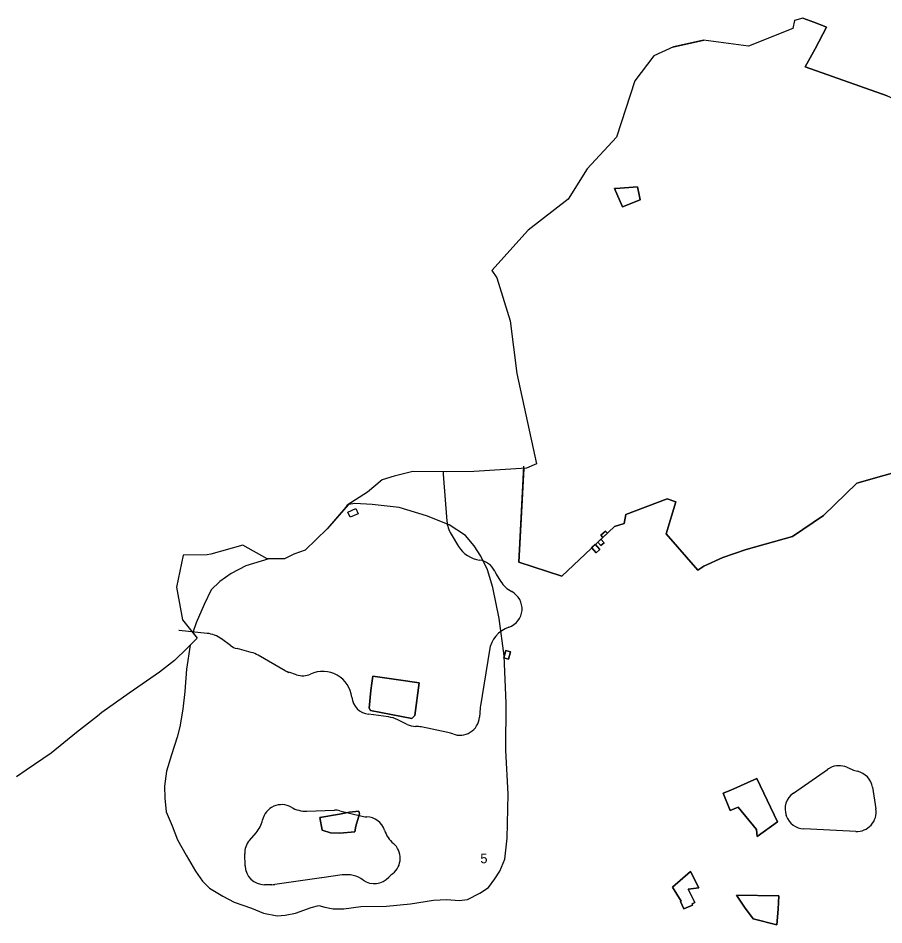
# Model space of a CAD drawing. Extents: x -445049 to -436194, y -1142460 to -1129816.
# Drawn here: x -443912 to -443023, y -1132330 to -1131398 of the extents above; entities that cross this region are included whole.
import ezdxf

# ---------------------------------------------------------------- set-up
doc = ezdxf.new("R2010")
doc.units = 0
for name, color, linetype in [('Vrstva 23', 7, 'Continuous'), ('Vrstva 51', 7, 'Continuous'), ('Vrstva 7', 7, 'Continuous'), ('Vrstva 8', 7, 'Continuous'), ('Vrstva 9', 7, 'Continuous')]:
    doc.layers.add(name, color=color, linetype=linetype)

msp = doc.modelspace()

# ---------------------------------------------------------------- linework, layer by layer
at = {"layer": 'Vrstva 23'}
for p, q in [((-443475.15, -1131866.8), (-443471.51, -1131914.89)), ((-443467.2, -1131928.26), (-443459.47, -1131940.92)), ((-443420.75, -1131969.45), (-443416.3, -1131976.64)), ((-443717.67, -1132030.24), (-443746.42, -1132027.28)), ((-443693.62, -1132042.73), (-443703.08, -1132035.84)), ((-443672.36, -1132049.78), (-443686.98, -1132045.89)), ((-443427.86, -1132047.57), (-443437.12, -1132104.61)), ((-443637.39, -1132068.59), (-443665.19, -1132052.72)), ((-443625.82, -1132072.79), (-443633.65, -1132070.24)), ((-443437.42, -1132107.15), (-443438.12, -1132116.33)), ((-443531.32, -1132116.07), (-443551.89, -1132113.37)), ((-443512.32, -1132123.69), (-443521.9, -1132118.94)), ((-443470.35, -1132131.96), (-443497.76, -1132126.37)), ((-443115.67, -1132194.27), (-443080.76, -1132169.96)), ((-443078.4, -1132168.54), (-443077.85, -1132168.26)), ((-443060.79, -1132167.75), (-443055.44, -1132170.08)), ((-443034.44, -1132188.31), (-443030.95, -1132210.57)), ((-443615.16, -1132212.82), (-443586.81, -1132211.84)), ((-443581.29, -1132212.42), (-443560.02, -1132217.71)), ((-443122.96, -1132217.73), (-443123.1, -1132217.33)), ((-443674.24, -1132242.99), (-443667.43, -1132235.14)), ((-443084.92, -1132232.05), (-443105.07, -1132231.06)), ((-443051.67, -1132233.64), (-443084.89, -1132232.05)), ((-443678.74, -1132268.92), (-443679.12, -1132256.7)), ((-443600.21, -1132281.21), (-443648.27, -1132288.12)), ((-443578.93, -1132278.3), (-443600.01, -1132281.18)), ((-443651.15, -1132288.32), (-443658.79, -1132288.31))]:
    msp.add_line(p, q, dxfattribs=at)
for centre, radius, start, end in [((-443445.23, -1131864.54), 30, 179.2383, 184.32397), ((-443441.59, -1131912.63), 30, 184.32397, 211.39988), ((-443433.87, -1131925.29), 30, 211.39988, 262.34732), ((-443440.53, -1131974.85), 20, 25.04438, 82.34732), ((-443395.23, -1131953.68), 30, 205.04438, 211.71501), ((-443390.78, -1131960.87), 30, 211.71501, 241.97229), ((-443414.28, -1132005.01), 20, 288.69459, 61.97229), ((-443749.5, -1132057.12), 30, 84.11683, 84.49329), ((-443720.75, -1132060.09), 30, 53.93356, 84.11683), ((-443398.25, -1132052.37), 30, 108.69459, 170.78246), ((-443681.85, -1132026.56), 20, 233.93356, 255.12335), ((-443680.06, -1132078.77), 30, 60.27268, 75.12335), ((-443627.47, -1132051.22), 20, 240.27268, 252.00897), ((-443598.96, -1132099.29), 30, 6.59723, 114.43788), ((-443619.64, -1132053.76), 20, 252.00897, 294.43788), ((-443549.29, -1132093.54), 20, 186.59723, 262.51376), ((-443407.51, -1132109.42), 30, 170.78246, 175.65272), ((-443535.23, -1132145.82), 30, 63.62647, 82.51376), ((-443458.06, -1132114.82), 20, 248.55867, 355.65272), ((-443503.44, -1132105.77), 20, 243.62647, 269.6398), ((-443503.75, -1132155.77), 30, 78.47906, 89.6398), ((-443476.34, -1132161.36), 30, 68.55867, 78.47906), ((-443069.33, -1132186.37), 20, 116.98135, 124.856), ((-443068.78, -1132186.09), 20, 66.47035, 116.98135), ((-443043.46, -1132142.57), 30, 246.47035, 257.5946), ((-443054.2, -1132191.41), 20, 8.919, 77.5946), ((-443104.24, -1132210.68), 20, 124.856, 199.4132), ((-443641.24, -1132226.11), 20, 59.94181, 167.73285), ((-443616.2, -1132182.83), 30, 239.94181, 271.9806), ((-443586.12, -1132231.82), 20, 76.02756, 91.9806), ((-443552.77, -1132188.6), 30, 256.02756, 267.99116), ((-443554.53, -1132238.56), 20, 18.04103, 87.99116), ((-443104.09, -1132211.09), 20, 199.4132, 267.18654), ((-443050.71, -1132213.67), 20, 267.25919, 8.919), ((-443690.1, -1132215.49), 30, 319.07827, 347.73285), ((-443506.98, -1132223.08), 30, 198.04103, 229.61742), ((-443083.94, -1132212.08), 20, 267.18654, 267.25919), ((-443659.13, -1132256.09), 20, 139.07827, 181.75911), ((-443539.38, -1132261.17), 20, 307.92905, 49.61742), ((-443658.75, -1132268.31), 20, 181.75911, 269.90427), ((-443595.95, -1132310.91), 30, 97.78127, 98.17651), ((-443574.86, -1132308.03), 30, 54.61036, 97.78127), ((-443545.91, -1132267.27), 20, 234.61036, 318.17982), ((-443508.64, -1132300.61), 30, 127.92905, 138.17982), ((-443651.12, -1132268.32), 20, 269.90427, 278.17651)]:
    msp.add_arc(centre, radius, start, end, dxfattribs=at)
at = {"layer": 'Vrstva 51'}
msp.add_lwpolyline([(-443572.42, -1131897.76), (-443594.49, -1131922.99), (-443616.95, -1131944.89), (-443628.48, -1131948.87), (-443638.18, -1131953.77), (-443654.2, -1131953.68), (-443677.95, -1131960.91), (-443692.88, -1131968.79), (-443704.54, -1131976.92), (-443713.38, -1131985.67), (-443720.65, -1132000.68), (-443729.01, -1132019.29), (-443732.41, -1132029.28), (-443727.75, -1132035.14), (-443735.16, -1132042.47), (-443738.73, -1132066.87), (-443740.48, -1132090.07), (-443742.64, -1132107.92), (-443745.64, -1132126.12), (-443748.5, -1132136.96), (-443754.36, -1132154.94), (-443759.31, -1132171.76), (-443761.29, -1132187.17), (-443760.98, -1132199.47), (-443759.58, -1132213.5), (-443753.7, -1132227.86), (-443748.23, -1132242.19), (-443739.18, -1132258.01), (-443729.76, -1132274.28), (-443722.36, -1132284.66), (-443715.11, -1132291.76), (-443701.42, -1132300.15), (-443690.01, -1132306.33), (-443672.06, -1132312.6), (-443659.74, -1132317.62), (-443645.62, -1132320.32), (-443637.39, -1132319.71), (-443626.99, -1132317.62), (-443611.01, -1132311.87), (-443603.06, -1132309.6), (-443596.64, -1132311.31), (-443588.18, -1132313.17), (-443577.13, -1132313.19), (-443559.75, -1132310.81), (-443533.52, -1132310.32), (-443508.79, -1132308.09), (-443485.15, -1132304.14), (-443471.6, -1132303.52), (-443458.98, -1132304.46), (-443450.31, -1132303.48), (-443437.55, -1132297.07), (-443428.91, -1132291.17), (-443422.1, -1132282.27), (-443417.01, -1132274.46), (-443411.99, -1132262.15), (-443409.56, -1132240.63), (-443408.6, -1132195.27), (-443410.94, -1132150.06), (-443410.58, -1132101.78), (-443412.67, -1132053.32), (-443417.96, -1132014.85), (-443424.18, -1131983.27), (-443429.76, -1131964.83), (-443436.48, -1131950.82), (-443443.48, -1131940.47), (-443452.49, -1131929.56), (-443469.29, -1131918.88), (-443492.32, -1131909.37), (-443520.35, -1131901.12), (-443548.35, -1131897.79), (-443565.88, -1131896.88)], close=True, dxfattribs=at)
at = {"layer": 'Vrstva 7'}
for points in [[(-443106.12, -1131398.41), (-443114.71, -1131400.93), (-443116.42, -1131408.94), (-443161.64, -1131427.27), (-443207.88, -1131421.18), (-443238.79, -1131427.9), (-443259.15, -1131437.15), (-443278.58, -1131462.76), (-443297.46, -1131520.49), (-443327.59, -1131553.33), (-443347.05, -1131584.42), (-443388.09, -1131616.17), (-443425.49, -1131657.44), (-443420.03, -1131665.04), (-443406.44, -1131709.38), (-443399.66, -1131763.33), (-443379.47, -1131856.15), (-443389.59, -1131860.69), (-443443.78, -1131863.94), (-443472.08, -1131864.36), (-443506.55, -1131863.91), (-443525.54, -1131868.7), (-443537.86, -1131872.43), (-443552.93, -1131885.12), (-443573.87, -1131898.7), (-443575.38, -1131900.47), (-443594.49, -1131922.99), (-443616.95, -1131944.89), (-443628.48, -1131948.87), (-443638.18, -1131953.77), (-443655.99, -1131953.67), (-443680.94, -1131939.56), (-443713.85, -1131949.02), (-443717.48, -1131949.61), (-443742.21, -1131949.8), (-443749.19, -1131982.83), (-443748.48, -1131986.52), (-443742.79, -1132016.22), (-443727.75, -1132035.14), (-443740.49, -1132047.74), (-443748.61, -1132055.57), (-443751.12, -1132058), (-443766.44, -1132070.14), (-443797.62, -1132091.8), (-443825.8, -1132111.44), (-443830.09, -1132115.31), (-443851.84, -1132132), (-443877.88, -1132153.33), (-443903.47, -1132170.82), (-443913.53, -1132177.67)], [(-443019.31, -1131478.11), (-443103.67, -1131448.32), (-443093.18, -1131429.88), (-443081.74, -1131407.73), (-443084.15, -1131406.8), (-443094.83, -1131402.72), (-443106.12, -1131398.41), (-443114.71, -1131400.93), (-443114.71, -1131400.93), (-443116.42, -1131408.94), (-443161.64, -1131427.27), (-443207.88, -1131421.18), (-443238.79, -1131427.9)], [(-443019.31, -1131478.11), (-443103.67, -1131448.32), (-443093.18, -1131429.88), (-443081.74, -1131407.73), (-443084.15, -1131406.8), (-443094.83, -1131402.72), (-443106.12, -1131398.41), (-443114.71, -1131400.93), (-443114.71, -1131400.93)], [(-443106.12, -1131398.41), (-443094.83, -1131402.72), (-443084.15, -1131406.8), (-443081.74, -1131407.73), (-443093.18, -1131429.88), (-443103.67, -1131448.32), (-443019.31, -1131478.11), (-442974.53, -1131497.84), (-442902.15, -1131529.1), (-442888.68, -1131535.01), (-442886.09, -1131536.13), (-442927.75, -1131581.75), (-442952.33, -1131605.18), (-442926.2, -1131613.08), (-442916.62, -1131615.98), (-442893.46, -1131628.44), (-442888.22, -1131631.26), (-442860.09, -1131646.4), (-442799.95, -1131665.86), (-442788.53, -1131669.56), (-442758.56, -1131679.26), (-442813.44, -1131728.66), (-442858.75, -1131769.44)], [(-443114.71, -1131400.93), (-443116.42, -1131408.94), (-443161.64, -1131427.27), (-443207.88, -1131421.18), (-443238.79, -1131427.9), (-443259.15, -1131437.15), (-443278.58, -1131462.76), (-443297.46, -1131520.49), (-443327.59, -1131553.33), (-443347.05, -1131584.42), (-443388.09, -1131616.17), (-443425.49, -1131657.44), (-443420.03, -1131665.04), (-443406.44, -1131709.38), (-443399.66, -1131763.33), (-443379.47, -1131856.15), (-443389.59, -1131860.69), (-443443.78, -1131863.94), (-443472.08, -1131864.36), (-443506.55, -1131863.91), (-443525.54, -1131868.7), (-443537.86, -1131872.43), (-443552.93, -1131885.12), (-443573.87, -1131898.7), (-443575.38, -1131900.47), (-443594.49, -1131922.99), (-443616.95, -1131944.89), (-443628.48, -1131948.87), (-443638.18, -1131953.77), (-443655.99, -1131953.67), (-443680.94, -1131939.56), (-443713.85, -1131949.02), (-443717.48, -1131949.61), (-443742.21, -1131949.8), (-443749.19, -1131982.83), (-443748.48, -1131986.52), (-443742.79, -1132016.22), (-443727.75, -1132035.14), (-443740.49, -1132047.74), (-443748.61, -1132055.57), (-443751.12, -1132058), (-443766.44, -1132070.14), (-443797.62, -1132091.8), (-443825.8, -1132111.44), (-443830.09, -1132115.31), (-443851.84, -1132132), (-443877.88, -1132153.33), (-443903.47, -1132170.82), (-443913.53, -1132177.67)], [(-443114.76, -1131400.94), (-443114.71, -1131400.93)], [(-443239.89, -1131428.14), (-443207.7, -1131421.15)], [(-443238.79, -1131427.9), (-443259.15, -1131437.15), (-443278.58, -1131462.76), (-443297.46, -1131520.49), (-443327.59, -1131553.33), (-443347.05, -1131584.42), (-443388.09, -1131616.17), (-443425.49, -1131657.44), (-443420.03, -1131665.04), (-443406.44, -1131709.38), (-443399.66, -1131763.33), (-443379.47, -1131856.15), (-443389.59, -1131860.69), (-443443.78, -1131863.94), (-443472.08, -1131864.36), (-443506.55, -1131863.91), (-443525.54, -1131868.7), (-443537.86, -1131872.43), (-443552.93, -1131885.12), (-443573.87, -1131898.7), (-443575.38, -1131900.47), (-443594.49, -1131922.99), (-443616.95, -1131944.89), (-443628.48, -1131948.87), (-443638.18, -1131953.77), (-443655.99, -1131953.67), (-443680.94, -1131939.56), (-443713.85, -1131949.02), (-443717.48, -1131949.61), (-443742.21, -1131949.8), (-443749.19, -1131982.83), (-443748.48, -1131986.52), (-443742.79, -1132016.22), (-443727.75, -1132035.14), (-443740.49, -1132047.74), (-443748.61, -1132055.57), (-443751.12, -1132058), (-443766.44, -1132070.14), (-443797.62, -1132091.8), (-443825.8, -1132111.44), (-443830.09, -1132115.31), (-443851.84, -1132132), (-443877.88, -1132153.33), (-443903.47, -1132170.82), (-443913.53, -1132177.67)], [(-443275.68, -1131571.49), (-443273.93, -1131579.97), (-443272.88, -1131585.04), (-443291.32, -1131592.19), (-443299.38, -1131573.45), (-443297.91, -1131573.32), (-443275.68, -1131571.49)], [(-443291.32, -1131592.19), (-443299.38, -1131573.45), (-443297.91, -1131573.32), (-443275.68, -1131571.49), (-443273.93, -1131579.97), (-443272.88, -1131585.04), (-443291.32, -1131592.19)], [(-443273.93, -1131579.97), (-443272.88, -1131585.04), (-443291.32, -1131592.19), (-443299.38, -1131573.45), (-443297.91, -1131573.32), (-443275.68, -1131571.49), (-443273.93, -1131579.97)], [(-443275.68, -1131571.49), (-443273.93, -1131579.97), (-443272.88, -1131585.04), (-443291.32, -1131592.19), (-443299.38, -1131573.45), (-443297.91, -1131573.32), (-443275.68, -1131571.49)], [(-443570.89, -1131910.87), (-443573.15, -1131905.64), (-443564.98, -1131902.12), (-443562.72, -1131907.35), (-443570.89, -1131910.87)], [(-443308.59, -1131925.1), (-443306.55, -1131927.36), (-443311.4, -1131931.75), (-443313.45, -1131929.49), (-443308.59, -1131925.1)], [(-443319.06, -1131938.68), (-443314.27, -1131943.98), (-443318.05, -1131947.4), (-443322.85, -1131942.1), (-443319.06, -1131938.68)], [(-443313.28, -1131933.45), (-443309.96, -1131937.12), (-443313.3, -1131940.14), (-443316.62, -1131936.47), (-443313.28, -1131933.45)], [(-443406.13, -1132049.27), (-443408.23, -1132056.78), (-443412.98, -1132055.45), (-443410.88, -1132047.95), (-443406.13, -1132049.27)], [(-443499.8, -1132080.89), (-443504.4, -1132114.58), (-443507.45, -1132117.77), (-443549.76, -1132109.44), (-443551.21, -1132106.87), (-443549.45, -1132088.95), (-443548.71, -1132081.39), (-443547.68, -1132074.2), (-443521.17, -1132078), (-443499.8, -1132080.89)], [(-443521.17, -1132078), (-443499.8, -1132080.89), (-443504.4, -1132114.58), (-443507.45, -1132117.77), (-443549.76, -1132109.44), (-443551.21, -1132106.87), (-443549.45, -1132088.95), (-443548.71, -1132081.39), (-443547.68, -1132074.2), (-443521.17, -1132078)], [(-443499.8, -1132080.89), (-443504.4, -1132114.58), (-443507.45, -1132117.77), (-443549.76, -1132109.44), (-443551.21, -1132106.87), (-443549.45, -1132088.95), (-443548.71, -1132081.39), (-443547.68, -1132074.2), (-443521.17, -1132078), (-443499.8, -1132080.89)], [(-443548.71, -1132081.39), (-443547.68, -1132074.2), (-443521.17, -1132078), (-443499.8, -1132080.89), (-443504.4, -1132114.58), (-443507.45, -1132117.77), (-443549.76, -1132109.44), (-443551.21, -1132106.87), (-443549.45, -1132088.95), (-443548.71, -1132081.39)], [(-443153.2, -1132179.22), (-443131.83, -1132223.89), (-443153.02, -1132238.75), (-443153.54, -1132231.61), (-443172.52, -1132208.83), (-443180.71, -1132212.05), (-443187.66, -1132194.36), (-443179.84, -1132191.22), (-443153.2, -1132179.22)], [(-443172.52, -1132208.83), (-443180.71, -1132212.05), (-443187.66, -1132194.36), (-443179.84, -1132191.22), (-443153.2, -1132179.22), (-443131.83, -1132223.89), (-443153.02, -1132238.75), (-443153.54, -1132231.61), (-443172.52, -1132208.83)], [(-443153.54, -1132231.61), (-443172.52, -1132208.83), (-443180.71, -1132212.05), (-443187.66, -1132194.36), (-443179.84, -1132191.22), (-443153.2, -1132179.22), (-443131.83, -1132223.89), (-443153.02, -1132238.75), (-443153.54, -1132231.61)], [(-443131.83, -1132223.89), (-443153.02, -1132238.75), (-443153.54, -1132231.61), (-443172.52, -1132208.83), (-443180.71, -1132212.05), (-443187.66, -1132194.36), (-443179.84, -1132191.22), (-443153.2, -1132179.22), (-443131.83, -1132223.89)], [(-443562.02, -1132212.92), (-443561.38, -1132215.63), (-443564.99, -1132228.34), (-443566.01, -1132233.97), (-443581.52, -1132235.27), (-443591.13, -1132235.01), (-443599.54, -1132232.26), (-443601.92, -1132219.46), (-443581.84, -1132215.84), (-443571.49, -1132213.97), (-443562.02, -1132212.92)], [(-443581.84, -1132215.84), (-443571.49, -1132213.97), (-443562.02, -1132212.92), (-443561.38, -1132215.63), (-443564.99, -1132228.34), (-443566.01, -1132233.97), (-443581.52, -1132235.27), (-443591.13, -1132235.01), (-443599.54, -1132232.26), (-443601.92, -1132219.46), (-443581.84, -1132215.84)], [(-443601.92, -1132219.46), (-443581.84, -1132215.84), (-443571.49, -1132213.97), (-443562.02, -1132212.92), (-443561.38, -1132215.63), (-443564.99, -1132228.34), (-443566.01, -1132233.97), (-443581.52, -1132235.27), (-443591.13, -1132235.01), (-443599.54, -1132232.26), (-443601.92, -1132219.46)], [(-443599.54, -1132232.26), (-443601.92, -1132219.46), (-443581.84, -1132215.84), (-443571.49, -1132213.97), (-443562.02, -1132212.92), (-443561.38, -1132215.63), (-443564.99, -1132228.34), (-443566.01, -1132233.97), (-443581.52, -1132235.27), (-443591.13, -1132235.01), (-443599.54, -1132232.26)], [(-443221.28, -1132274.81), (-443212.79, -1132291.62), (-443223.56, -1132293.08), (-443216.83, -1132306.64), (-443219.67, -1132308.05), (-443219.17, -1132309.21), (-443228.34, -1132313.19), (-443231.7, -1132305.54), (-443231.03, -1132305.26), (-443239.73, -1132290.98), (-443221.28, -1132274.81)], [(-443239.73, -1132290.98), (-443221.28, -1132274.81), (-443212.79, -1132291.62), (-443223.56, -1132293.08), (-443216.83, -1132306.64), (-443219.67, -1132308.05), (-443219.17, -1132309.21), (-443228.34, -1132313.19), (-443231.7, -1132305.54), (-443231.03, -1132305.26), (-443239.73, -1132290.98)], [(-443219.17, -1132309.21), (-443228.34, -1132313.19), (-443231.7, -1132305.54), (-443231.03, -1132305.26), (-443239.73, -1132290.98), (-443221.28, -1132274.81), (-443212.79, -1132291.62), (-443223.56, -1132293.08), (-443216.83, -1132306.64), (-443219.67, -1132308.05), (-443219.17, -1132309.21)], [(-443219.67, -1132308.05), (-443219.17, -1132309.21), (-443228.34, -1132313.19), (-443231.7, -1132305.54), (-443231.03, -1132305.26), (-443239.73, -1132290.98), (-443221.28, -1132274.81), (-443212.79, -1132291.62), (-443223.56, -1132293.08), (-443216.83, -1132306.64), (-443219.67, -1132308.05)], [(-443130.57, -1132299.65), (-443131.31, -1132313.51), (-443132.73, -1132329.58), (-443157.13, -1132323.38), (-443165.76, -1132311.33), (-443174.05, -1132299.19), (-443130.57, -1132299.65)], [(-443174.05, -1132299.19), (-443130.57, -1132299.65), (-443131.31, -1132313.51), (-443132.73, -1132329.58), (-443157.13, -1132323.38), (-443165.76, -1132311.33), (-443174.05, -1132299.19)], [(-443165.76, -1132311.33), (-443174.05, -1132299.19), (-443130.57, -1132299.65), (-443131.31, -1132313.51), (-443132.73, -1132329.58), (-443157.13, -1132323.38), (-443165.76, -1132311.33)], [(-443174.05, -1132299.19), (-443130.57, -1132299.65), (-443131.31, -1132313.51), (-443132.73, -1132329.58), (-443157.13, -1132323.38), (-443165.76, -1132311.33), (-443174.05, -1132299.19)]]:
    msp.add_lwpolyline(points, dxfattribs=at)
for points in [[(-443275.68, -1131571.49), (-443297.91, -1131573.32), (-443299.38, -1131573.45), (-443291.32, -1131592.19), (-443272.88, -1131585.04), (-443273.93, -1131579.97)], [(-443573.15, -1131905.64), (-443564.98, -1131902.12), (-443562.72, -1131907.35), (-443570.89, -1131910.87)], [(-443308.59, -1131925.1), (-443313.45, -1131929.49), (-443311.4, -1131931.75), (-443306.55, -1131927.36)], [(-443319.06, -1131938.68), (-443322.85, -1131942.1), (-443318.05, -1131947.4), (-443314.27, -1131943.98)], [(-443313.28, -1131933.45), (-443316.62, -1131936.47), (-443313.3, -1131940.14), (-443309.96, -1131937.12)], [(-443406.13, -1132049.27), (-443410.88, -1132047.95), (-443412.98, -1132055.45), (-443408.23, -1132056.78)], [(-443499.8, -1132080.89), (-443521.17, -1132078), (-443547.68, -1132074.2), (-443548.71, -1132081.39), (-443549.45, -1132088.95), (-443551.21, -1132106.87), (-443549.76, -1132109.44), (-443507.45, -1132117.77), (-443504.4, -1132114.58)], [(-443153.2, -1132179.22), (-443179.84, -1132191.22), (-443187.66, -1132194.36), (-443180.71, -1132212.05), (-443172.52, -1132208.83), (-443153.54, -1132231.61), (-443153.02, -1132238.75), (-443131.83, -1132223.89)], [(-443562.02, -1132212.92), (-443571.49, -1132213.97), (-443581.84, -1132215.84), (-443601.92, -1132219.46), (-443599.54, -1132232.26), (-443591.13, -1132235.01), (-443581.52, -1132235.27), (-443566.01, -1132233.97), (-443564.99, -1132228.34), (-443561.38, -1132215.63)], [(-443221.28, -1132274.81), (-443239.73, -1132290.98), (-443231.03, -1132305.26), (-443231.7, -1132305.54), (-443228.34, -1132313.19), (-443219.17, -1132309.21), (-443219.67, -1132308.05), (-443216.83, -1132306.64), (-443223.56, -1132293.08), (-443212.79, -1132291.62)], [(-443130.57, -1132299.65), (-443174.05, -1132299.19), (-443165.76, -1132311.33), (-443157.13, -1132323.38), (-443132.73, -1132329.58), (-443131.31, -1132313.51)]]:
    msp.add_lwpolyline(points, close=True, dxfattribs=at)
at = {"layer": 'Vrstva 8'}
msp.add_lwpolyline([(-443392.54, -1131860.87), (-443397.48, -1131957.17), (-443353.42, -1131971.39), (-443299.24, -1131920.46), (-443289.59, -1131917.32), (-443287.89, -1131908.07), (-443245.35, -1131891.96), (-443236.54, -1131894.98), (-443246.43, -1131928.02), (-443213.64, -1131965.17), (-443207.51, -1131961.18), (-443188.23, -1131952.25), (-443164.1, -1131944.18), (-443116.7, -1131930.67), (-443084.75, -1131909.35), (-443050.67, -1131876.14), (-442994.94, -1131860.38)], dxfattribs=at)
at = {"layer": 'Vrstva 9'}
msp.add_lwpolyline([(-442994.94, -1131860.38), (-443050.67, -1131876.14), (-443084.75, -1131909.35), (-443116.7, -1131930.67), (-443164.1, -1131944.18), (-443188.23, -1131952.25), (-443207.51, -1131961.18), (-443213.64, -1131965.17), (-443246.43, -1131928.02), (-443236.54, -1131894.98), (-443245.35, -1131891.96), (-443287.89, -1131908.07), (-443289.59, -1131917.32), (-443299.24, -1131920.46), (-443353.42, -1131971.39), (-443397.48, -1131957.17), (-443392.43, -1131858.65)], dxfattribs=at)

# ---------------------------------------------------------------- texts
at = {"layer": 'Vrstva 51'}
msp.add_text('5', height=10, dxfattribs=at).set_placement((-443437.17, -1132266.31))

doc.saveas('drawing.dxf')
